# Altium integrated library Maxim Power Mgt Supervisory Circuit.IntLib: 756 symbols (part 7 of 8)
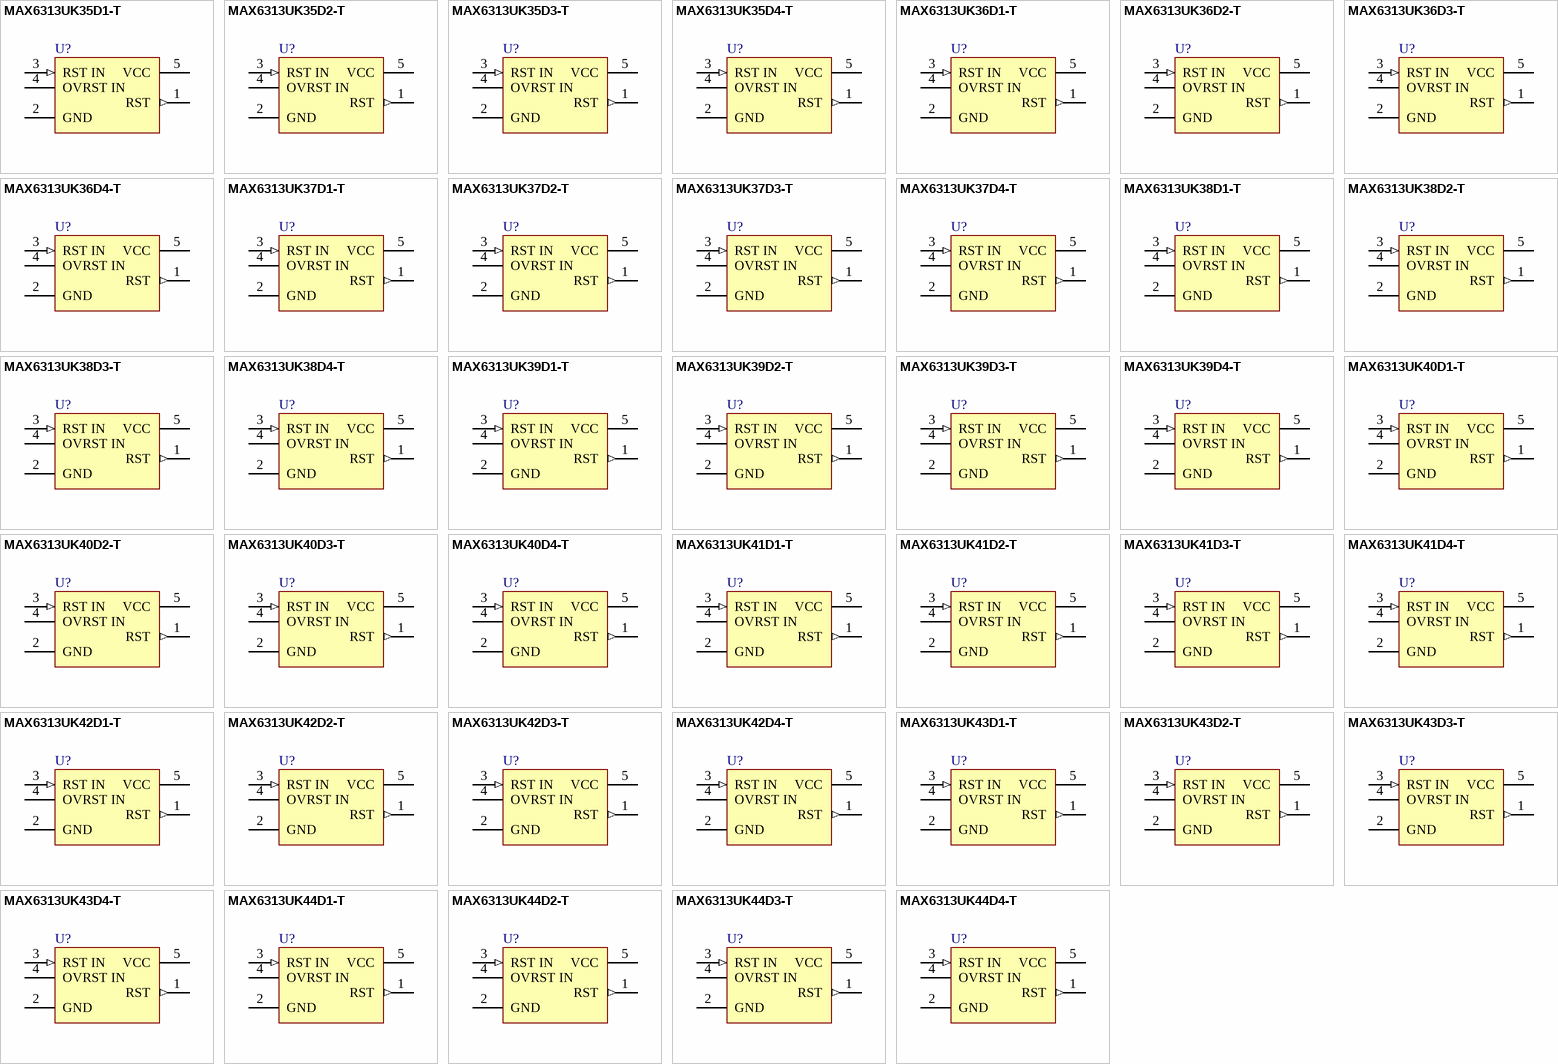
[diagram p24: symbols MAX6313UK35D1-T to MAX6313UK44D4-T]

## MAX6313UK36D3-T
designator U?
5-Pin, Multiple-Input, Programmable Reset IC
footprint SOT23-5_N (SOT23, 5-Leads, Body 2.9x1.6mm, Pitch 0.95mm, Lead Span 2.8mm, IPC Medium Density)
footprint SOT23-5_L (SOT23, 5-Leads, Body 2.9x1.6mm, Pitch 0.95mm, Lead Span 2.8mm, IPC High Density)
footprint SOT23-5_M (SOT23, 5-Leads, Body 2.9x1.6mm, Pitch 0.95mm, Lead Span 2.8mm, IPC Low Density)
pins: 1 RST (out), 2 GND (power), 3 RST IN (in), 4 OVRST IN, 5 VCC (power)

## MAX6313UK36D4-T
designator U?
5-Pin, Multiple-Input, Programmable Reset IC
footprint SOT23-5_N (SOT23, 5-Leads, Body 2.9x1.6mm, Pitch 0.95mm, Lead Span 2.8mm, IPC Medium Density)
footprint SOT23-5_L (SOT23, 5-Leads, Body 2.9x1.6mm, Pitch 0.95mm, Lead Span 2.8mm, IPC High Density)
footprint SOT23-5_M (SOT23, 5-Leads, Body 2.9x1.6mm, Pitch 0.95mm, Lead Span 2.8mm, IPC Low Density)
pins: 1 RST (out), 2 GND (power), 3 RST IN (in), 4 OVRST IN, 5 VCC (power)

## MAX6313UK37D1-T
designator U?
5-Pin, Multiple-Input, Programmable Reset IC
footprint SOT23-5_N (SOT23, 5-Leads, Body 2.9x1.6mm, Pitch 0.95mm, Lead Span 2.8mm, IPC Medium Density)
footprint SOT23-5_L (SOT23, 5-Leads, Body 2.9x1.6mm, Pitch 0.95mm, Lead Span 2.8mm, IPC High Density)
footprint SOT23-5_M (SOT23, 5-Leads, Body 2.9x1.6mm, Pitch 0.95mm, Lead Span 2.8mm, IPC Low Density)
pins: 1 RST (out), 2 GND (power), 3 RST IN (in), 4 OVRST IN, 5 VCC (power)

## MAX6313UK37D2-T
designator U?
5-Pin, Multiple-Input, Programmable Reset IC
footprint SOT23-5_N (SOT23, 5-Leads, Body 2.9x1.6mm, Pitch 0.95mm, Lead Span 2.8mm, IPC Medium Density)
footprint SOT23-5_L (SOT23, 5-Leads, Body 2.9x1.6mm, Pitch 0.95mm, Lead Span 2.8mm, IPC High Density)
footprint SOT23-5_M (SOT23, 5-Leads, Body 2.9x1.6mm, Pitch 0.95mm, Lead Span 2.8mm, IPC Low Density)
pins: 1 RST (out), 2 GND (power), 3 RST IN (in), 4 OVRST IN, 5 VCC (power)

## MAX6313UK37D3-T
designator U?
5-Pin, Multiple-Input, Programmable Reset IC
footprint SOT23-5_N (SOT23, 5-Leads, Body 2.9x1.6mm, Pitch 0.95mm, Lead Span 2.8mm, IPC Medium Density)
footprint SOT23-5_L (SOT23, 5-Leads, Body 2.9x1.6mm, Pitch 0.95mm, Lead Span 2.8mm, IPC High Density)
footprint SOT23-5_M (SOT23, 5-Leads, Body 2.9x1.6mm, Pitch 0.95mm, Lead Span 2.8mm, IPC Low Density)
pins: 1 RST (out), 2 GND (power), 3 RST IN (in), 4 OVRST IN, 5 VCC (power)

## MAX6313UK37D4-T
designator U?
5-Pin, Multiple-Input, Programmable Reset IC
footprint SOT23-5_N (SOT23, 5-Leads, Body 2.9x1.6mm, Pitch 0.95mm, Lead Span 2.8mm, IPC Medium Density)
footprint SOT23-5_L (SOT23, 5-Leads, Body 2.9x1.6mm, Pitch 0.95mm, Lead Span 2.8mm, IPC High Density)
footprint SOT23-5_M (SOT23, 5-Leads, Body 2.9x1.6mm, Pitch 0.95mm, Lead Span 2.8mm, IPC Low Density)
pins: 1 RST (out), 2 GND (power), 3 RST IN (in), 4 OVRST IN, 5 VCC (power)

## MAX6313UK38D1-T
designator U?
5-Pin, Multiple-Input, Programmable Reset IC
footprint SOT23-5_N (SOT23, 5-Leads, Body 2.9x1.6mm, Pitch 0.95mm, Lead Span 2.8mm, IPC Medium Density)
footprint SOT23-5_L (SOT23, 5-Leads, Body 2.9x1.6mm, Pitch 0.95mm, Lead Span 2.8mm, IPC High Density)
footprint SOT23-5_M (SOT23, 5-Leads, Body 2.9x1.6mm, Pitch 0.95mm, Lead Span 2.8mm, IPC Low Density)
pins: 1 RST (out), 2 GND (power), 3 RST IN (in), 4 OVRST IN, 5 VCC (power)

## MAX6313UK38D2-T
designator U?
5-Pin, Multiple-Input, Programmable Reset IC
footprint SOT23-5_N (SOT23, 5-Leads, Body 2.9x1.6mm, Pitch 0.95mm, Lead Span 2.8mm, IPC Medium Density)
footprint SOT23-5_L (SOT23, 5-Leads, Body 2.9x1.6mm, Pitch 0.95mm, Lead Span 2.8mm, IPC High Density)
footprint SOT23-5_M (SOT23, 5-Leads, Body 2.9x1.6mm, Pitch 0.95mm, Lead Span 2.8mm, IPC Low Density)
pins: 1 RST (out), 2 GND (power), 3 RST IN (in), 4 OVRST IN, 5 VCC (power)

## MAX6313UK38D3-T
designator U?
5-Pin, Multiple-Input, Programmable Reset IC
footprint SOT23-5_N (SOT23, 5-Leads, Body 2.9x1.6mm, Pitch 0.95mm, Lead Span 2.8mm, IPC Medium Density)
footprint SOT23-5_L (SOT23, 5-Leads, Body 2.9x1.6mm, Pitch 0.95mm, Lead Span 2.8mm, IPC High Density)
footprint SOT23-5_M (SOT23, 5-Leads, Body 2.9x1.6mm, Pitch 0.95mm, Lead Span 2.8mm, IPC Low Density)
pins: 1 RST (out), 2 GND (power), 3 RST IN (in), 4 OVRST IN, 5 VCC (power)

## MAX6313UK38D4-T
designator U?
5-Pin, Multiple-Input, Programmable Reset IC
footprint SOT23-5_N (SOT23, 5-Leads, Body 2.9x1.6mm, Pitch 0.95mm, Lead Span 2.8mm, IPC Medium Density)
footprint SOT23-5_L (SOT23, 5-Leads, Body 2.9x1.6mm, Pitch 0.95mm, Lead Span 2.8mm, IPC High Density)
footprint SOT23-5_M (SOT23, 5-Leads, Body 2.9x1.6mm, Pitch 0.95mm, Lead Span 2.8mm, IPC Low Density)
pins: 1 RST (out), 2 GND (power), 3 RST IN (in), 4 OVRST IN, 5 VCC (power)

## MAX6313UK39D1-T
designator U?
5-Pin, Multiple-Input, Programmable Reset IC
footprint SOT23-5_N (SOT23, 5-Leads, Body 2.9x1.6mm, Pitch 0.95mm, Lead Span 2.8mm, IPC Medium Density)
footprint SOT23-5_L (SOT23, 5-Leads, Body 2.9x1.6mm, Pitch 0.95mm, Lead Span 2.8mm, IPC High Density)
footprint SOT23-5_M (SOT23, 5-Leads, Body 2.9x1.6mm, Pitch 0.95mm, Lead Span 2.8mm, IPC Low Density)
pins: 1 RST (out), 2 GND (power), 3 RST IN (in), 4 OVRST IN, 5 VCC (power)

## MAX6313UK39D2-T
designator U?
5-Pin, Multiple-Input, Programmable Reset IC
footprint SOT23-5_N (SOT23, 5-Leads, Body 2.9x1.6mm, Pitch 0.95mm, Lead Span 2.8mm, IPC Medium Density)
footprint SOT23-5_L (SOT23, 5-Leads, Body 2.9x1.6mm, Pitch 0.95mm, Lead Span 2.8mm, IPC High Density)
footprint SOT23-5_M (SOT23, 5-Leads, Body 2.9x1.6mm, Pitch 0.95mm, Lead Span 2.8mm, IPC Low Density)
pins: 1 RST (out), 2 GND (power), 3 RST IN (in), 4 OVRST IN, 5 VCC (power)

## MAX6313UK39D3-T
designator U?
5-Pin, Multiple-Input, Programmable Reset IC
footprint SOT23-5_N (SOT23, 5-Leads, Body 2.9x1.6mm, Pitch 0.95mm, Lead Span 2.8mm, IPC Medium Density)
footprint SOT23-5_L (SOT23, 5-Leads, Body 2.9x1.6mm, Pitch 0.95mm, Lead Span 2.8mm, IPC High Density)
footprint SOT23-5_M (SOT23, 5-Leads, Body 2.9x1.6mm, Pitch 0.95mm, Lead Span 2.8mm, IPC Low Density)
pins: 1 RST (out), 2 GND (power), 3 RST IN (in), 4 OVRST IN, 5 VCC (power)

## MAX6313UK39D4-T
designator U?
5-Pin, Multiple-Input, Programmable Reset IC
footprint SOT23-5_N (SOT23, 5-Leads, Body 2.9x1.6mm, Pitch 0.95mm, Lead Span 2.8mm, IPC Medium Density)
footprint SOT23-5_L (SOT23, 5-Leads, Body 2.9x1.6mm, Pitch 0.95mm, Lead Span 2.8mm, IPC High Density)
footprint SOT23-5_M (SOT23, 5-Leads, Body 2.9x1.6mm, Pitch 0.95mm, Lead Span 2.8mm, IPC Low Density)
pins: 1 RST (out), 2 GND (power), 3 RST IN (in), 4 OVRST IN, 5 VCC (power)

## MAX6313UK40D1-T
designator U?
5-Pin, Multiple-Input, Programmable Reset IC
footprint SOT23-5_N (SOT23, 5-Leads, Body 2.9x1.6mm, Pitch 0.95mm, Lead Span 2.8mm, IPC Medium Density)
footprint SOT23-5_L (SOT23, 5-Leads, Body 2.9x1.6mm, Pitch 0.95mm, Lead Span 2.8mm, IPC High Density)
footprint SOT23-5_M (SOT23, 5-Leads, Body 2.9x1.6mm, Pitch 0.95mm, Lead Span 2.8mm, IPC Low Density)
pins: 1 RST (out), 2 GND (power), 3 RST IN (in), 4 OVRST IN, 5 VCC (power)

## MAX6313UK40D2-T
designator U?
5-Pin, Multiple-Input, Programmable Reset IC
footprint SOT23-5_N (SOT23, 5-Leads, Body 2.9x1.6mm, Pitch 0.95mm, Lead Span 2.8mm, IPC Medium Density)
footprint SOT23-5_L (SOT23, 5-Leads, Body 2.9x1.6mm, Pitch 0.95mm, Lead Span 2.8mm, IPC High Density)
footprint SOT23-5_M (SOT23, 5-Leads, Body 2.9x1.6mm, Pitch 0.95mm, Lead Span 2.8mm, IPC Low Density)
pins: 1 RST (out), 2 GND (power), 3 RST IN (in), 4 OVRST IN, 5 VCC (power)

## MAX6313UK40D3-T
designator U?
5-Pin, Multiple-Input, Programmable Reset IC
footprint SOT23-5_N (SOT23, 5-Leads, Body 2.9x1.6mm, Pitch 0.95mm, Lead Span 2.8mm, IPC Medium Density)
footprint SOT23-5_L (SOT23, 5-Leads, Body 2.9x1.6mm, Pitch 0.95mm, Lead Span 2.8mm, IPC High Density)
footprint SOT23-5_M (SOT23, 5-Leads, Body 2.9x1.6mm, Pitch 0.95mm, Lead Span 2.8mm, IPC Low Density)
pins: 1 RST (out), 2 GND (power), 3 RST IN (in), 4 OVRST IN, 5 VCC (power)

## MAX6313UK40D4-T
designator U?
5-Pin, Multiple-Input, Programmable Reset IC
footprint SOT23-5_N (SOT23, 5-Leads, Body 2.9x1.6mm, Pitch 0.95mm, Lead Span 2.8mm, IPC Medium Density)
footprint SOT23-5_L (SOT23, 5-Leads, Body 2.9x1.6mm, Pitch 0.95mm, Lead Span 2.8mm, IPC High Density)
footprint SOT23-5_M (SOT23, 5-Leads, Body 2.9x1.6mm, Pitch 0.95mm, Lead Span 2.8mm, IPC Low Density)
pins: 1 RST (out), 2 GND (power), 3 RST IN (in), 4 OVRST IN, 5 VCC (power)

## MAX6313UK41D1-T
designator U?
5-Pin, Multiple-Input, Programmable Reset IC
footprint SOT23-5_N (SOT23, 5-Leads, Body 2.9x1.6mm, Pitch 0.95mm, Lead Span 2.8mm, IPC Medium Density)
footprint SOT23-5_L (SOT23, 5-Leads, Body 2.9x1.6mm, Pitch 0.95mm, Lead Span 2.8mm, IPC High Density)
footprint SOT23-5_M (SOT23, 5-Leads, Body 2.9x1.6mm, Pitch 0.95mm, Lead Span 2.8mm, IPC Low Density)
pins: 1 RST (out), 2 GND (power), 3 RST IN (in), 4 OVRST IN, 5 VCC (power)

## MAX6313UK41D2-T
designator U?
5-Pin, Multiple-Input, Programmable Reset IC
footprint SOT23-5_N (SOT23, 5-Leads, Body 2.9x1.6mm, Pitch 0.95mm, Lead Span 2.8mm, IPC Medium Density)
footprint SOT23-5_L (SOT23, 5-Leads, Body 2.9x1.6mm, Pitch 0.95mm, Lead Span 2.8mm, IPC High Density)
footprint SOT23-5_M (SOT23, 5-Leads, Body 2.9x1.6mm, Pitch 0.95mm, Lead Span 2.8mm, IPC Low Density)
pins: 1 RST (out), 2 GND (power), 3 RST IN (in), 4 OVRST IN, 5 VCC (power)

## MAX6313UK41D3-T
designator U?
5-Pin, Multiple-Input, Programmable Reset IC
footprint SOT23-5_N (SOT23, 5-Leads, Body 2.9x1.6mm, Pitch 0.95mm, Lead Span 2.8mm, IPC Medium Density)
footprint SOT23-5_L (SOT23, 5-Leads, Body 2.9x1.6mm, Pitch 0.95mm, Lead Span 2.8mm, IPC High Density)
footprint SOT23-5_M (SOT23, 5-Leads, Body 2.9x1.6mm, Pitch 0.95mm, Lead Span 2.8mm, IPC Low Density)
pins: 1 RST (out), 2 GND (power), 3 RST IN (in), 4 OVRST IN, 5 VCC (power)

## MAX6313UK41D4-T
designator U?
5-Pin, Multiple-Input, Programmable Reset IC
footprint SOT23-5_N (SOT23, 5-Leads, Body 2.9x1.6mm, Pitch 0.95mm, Lead Span 2.8mm, IPC Medium Density)
footprint SOT23-5_L (SOT23, 5-Leads, Body 2.9x1.6mm, Pitch 0.95mm, Lead Span 2.8mm, IPC High Density)
footprint SOT23-5_M (SOT23, 5-Leads, Body 2.9x1.6mm, Pitch 0.95mm, Lead Span 2.8mm, IPC Low Density)
pins: 1 RST (out), 2 GND (power), 3 RST IN (in), 4 OVRST IN, 5 VCC (power)

## MAX6313UK42D1-T
designator U?
5-Pin, Multiple-Input, Programmable Reset IC
footprint SOT23-5_N (SOT23, 5-Leads, Body 2.9x1.6mm, Pitch 0.95mm, Lead Span 2.8mm, IPC Medium Density)
footprint SOT23-5_L (SOT23, 5-Leads, Body 2.9x1.6mm, Pitch 0.95mm, Lead Span 2.8mm, IPC High Density)
footprint SOT23-5_M (SOT23, 5-Leads, Body 2.9x1.6mm, Pitch 0.95mm, Lead Span 2.8mm, IPC Low Density)
pins: 1 RST (out), 2 GND (power), 3 RST IN (in), 4 OVRST IN, 5 VCC (power)

## MAX6313UK42D2-T
designator U?
5-Pin, Multiple-Input, Programmable Reset IC
footprint SOT23-5_N (SOT23, 5-Leads, Body 2.9x1.6mm, Pitch 0.95mm, Lead Span 2.8mm, IPC Medium Density)
footprint SOT23-5_L (SOT23, 5-Leads, Body 2.9x1.6mm, Pitch 0.95mm, Lead Span 2.8mm, IPC High Density)
footprint SOT23-5_M (SOT23, 5-Leads, Body 2.9x1.6mm, Pitch 0.95mm, Lead Span 2.8mm, IPC Low Density)
pins: 1 RST (out), 2 GND (power), 3 RST IN (in), 4 OVRST IN, 5 VCC (power)

## MAX6313UK42D3-T
designator U?
5-Pin, Multiple-Input, Programmable Reset IC
footprint SOT23-5_N (SOT23, 5-Leads, Body 2.9x1.6mm, Pitch 0.95mm, Lead Span 2.8mm, IPC Medium Density)
footprint SOT23-5_L (SOT23, 5-Leads, Body 2.9x1.6mm, Pitch 0.95mm, Lead Span 2.8mm, IPC High Density)
footprint SOT23-5_M (SOT23, 5-Leads, Body 2.9x1.6mm, Pitch 0.95mm, Lead Span 2.8mm, IPC Low Density)
pins: 1 RST (out), 2 GND (power), 3 RST IN (in), 4 OVRST IN, 5 VCC (power)

## MAX6313UK42D4-T
designator U?
5-Pin, Multiple-Input, Programmable Reset IC
footprint SOT23-5_N (SOT23, 5-Leads, Body 2.9x1.6mm, Pitch 0.95mm, Lead Span 2.8mm, IPC Medium Density)
footprint SOT23-5_L (SOT23, 5-Leads, Body 2.9x1.6mm, Pitch 0.95mm, Lead Span 2.8mm, IPC High Density)
footprint SOT23-5_M (SOT23, 5-Leads, Body 2.9x1.6mm, Pitch 0.95mm, Lead Span 2.8mm, IPC Low Density)
pins: 1 RST (out), 2 GND (power), 3 RST IN (in), 4 OVRST IN, 5 VCC (power)

## MAX6313UK43D1-T
designator U?
5-Pin, Multiple-Input, Programmable Reset IC
footprint SOT23-5_N (SOT23, 5-Leads, Body 2.9x1.6mm, Pitch 0.95mm, Lead Span 2.8mm, IPC Medium Density)
footprint SOT23-5_L (SOT23, 5-Leads, Body 2.9x1.6mm, Pitch 0.95mm, Lead Span 2.8mm, IPC High Density)
footprint SOT23-5_M (SOT23, 5-Leads, Body 2.9x1.6mm, Pitch 0.95mm, Lead Span 2.8mm, IPC Low Density)
pins: 1 RST (out), 2 GND (power), 3 RST IN (in), 4 OVRST IN, 5 VCC (power)

## MAX6313UK43D2-T
designator U?
5-Pin, Multiple-Input, Programmable Reset IC
footprint SOT23-5_N (SOT23, 5-Leads, Body 2.9x1.6mm, Pitch 0.95mm, Lead Span 2.8mm, IPC Medium Density)
footprint SOT23-5_L (SOT23, 5-Leads, Body 2.9x1.6mm, Pitch 0.95mm, Lead Span 2.8mm, IPC High Density)
footprint SOT23-5_M (SOT23, 5-Leads, Body 2.9x1.6mm, Pitch 0.95mm, Lead Span 2.8mm, IPC Low Density)
pins: 1 RST (out), 2 GND (power), 3 RST IN (in), 4 OVRST IN, 5 VCC (power)

## MAX6313UK43D3-T
designator U?
5-Pin, Multiple-Input, Programmable Reset IC
footprint SOT23-5_N (SOT23, 5-Leads, Body 2.9x1.6mm, Pitch 0.95mm, Lead Span 2.8mm, IPC Medium Density)
footprint SOT23-5_L (SOT23, 5-Leads, Body 2.9x1.6mm, Pitch 0.95mm, Lead Span 2.8mm, IPC High Density)
footprint SOT23-5_M (SOT23, 5-Leads, Body 2.9x1.6mm, Pitch 0.95mm, Lead Span 2.8mm, IPC Low Density)
pins: 1 RST (out), 2 GND (power), 3 RST IN (in), 4 OVRST IN, 5 VCC (power)

## MAX6313UK43D4-T
designator U?
5-Pin, Multiple-Input, Programmable Reset IC
footprint SOT23-5_N (SOT23, 5-Leads, Body 2.9x1.6mm, Pitch 0.95mm, Lead Span 2.8mm, IPC Medium Density)
footprint SOT23-5_L (SOT23, 5-Leads, Body 2.9x1.6mm, Pitch 0.95mm, Lead Span 2.8mm, IPC High Density)
footprint SOT23-5_M (SOT23, 5-Leads, Body 2.9x1.6mm, Pitch 0.95mm, Lead Span 2.8mm, IPC Low Density)
pins: 1 RST (out), 2 GND (power), 3 RST IN (in), 4 OVRST IN, 5 VCC (power)

## MAX6313UK44D1-T
designator U?
5-Pin, Multiple-Input, Programmable Reset IC
footprint SOT23-5_N (SOT23, 5-Leads, Body 2.9x1.6mm, Pitch 0.95mm, Lead Span 2.8mm, IPC Medium Density)
footprint SOT23-5_L (SOT23, 5-Leads, Body 2.9x1.6mm, Pitch 0.95mm, Lead Span 2.8mm, IPC High Density)
footprint SOT23-5_M (SOT23, 5-Leads, Body 2.9x1.6mm, Pitch 0.95mm, Lead Span 2.8mm, IPC Low Density)
pins: 1 RST (out), 2 GND (power), 3 RST IN (in), 4 OVRST IN, 5 VCC (power)

## MAX6313UK44D2-T
designator U?
5-Pin, Multiple-Input, Programmable Reset IC
footprint SOT23-5_N (SOT23, 5-Leads, Body 2.9x1.6mm, Pitch 0.95mm, Lead Span 2.8mm, IPC Medium Density)
footprint SOT23-5_L (SOT23, 5-Leads, Body 2.9x1.6mm, Pitch 0.95mm, Lead Span 2.8mm, IPC High Density)
footprint SOT23-5_M (SOT23, 5-Leads, Body 2.9x1.6mm, Pitch 0.95mm, Lead Span 2.8mm, IPC Low Density)
pins: 1 RST (out), 2 GND (power), 3 RST IN (in), 4 OVRST IN, 5 VCC (power)

## MAX6313UK44D3-T
designator U?
5-Pin, Multiple-Input, Programmable Reset IC
footprint SOT23-5_N (SOT23, 5-Leads, Body 2.9x1.6mm, Pitch 0.95mm, Lead Span 2.8mm, IPC Medium Density)
footprint SOT23-5_L (SOT23, 5-Leads, Body 2.9x1.6mm, Pitch 0.95mm, Lead Span 2.8mm, IPC High Density)
footprint SOT23-5_M (SOT23, 5-Leads, Body 2.9x1.6mm, Pitch 0.95mm, Lead Span 2.8mm, IPC Low Density)
pins: 1 RST (out), 2 GND (power), 3 RST IN (in), 4 OVRST IN, 5 VCC (power)

## MAX6313UK44D4-T
designator U?
5-Pin, Multiple-Input, Programmable Reset IC
footprint SOT23-5_N (SOT23, 5-Leads, Body 2.9x1.6mm, Pitch 0.95mm, Lead Span 2.8mm, IPC Medium Density)
footprint SOT23-5_L (SOT23, 5-Leads, Body 2.9x1.6mm, Pitch 0.95mm, Lead Span 2.8mm, IPC High Density)
footprint SOT23-5_M (SOT23, 5-Leads, Body 2.9x1.6mm, Pitch 0.95mm, Lead Span 2.8mm, IPC Low Density)
pins: 1 RST (out), 2 GND (power), 3 RST IN (in), 4 OVRST IN, 5 VCC (power)

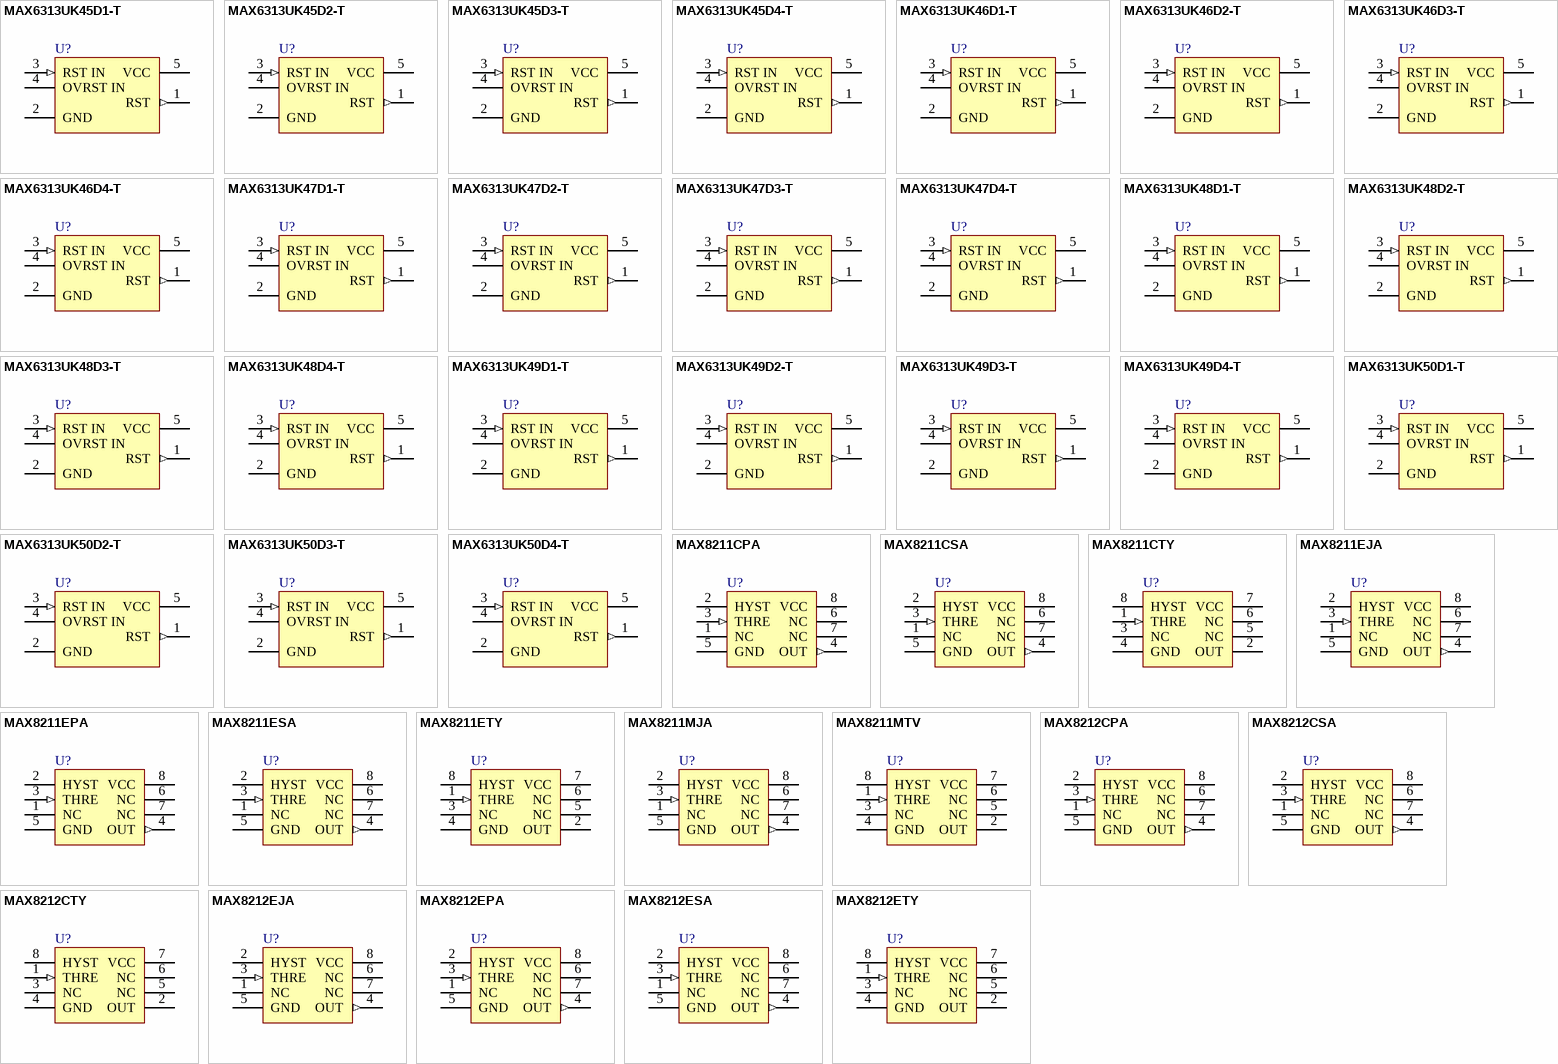
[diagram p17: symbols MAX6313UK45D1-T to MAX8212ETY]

## MAX6313UK45D1-T
designator U?
5-Pin, Multiple-Input, Programmable Reset IC
footprint SOT23-5_N (SOT23, 5-Leads, Body 2.9x1.6mm, Pitch 0.95mm, Lead Span 2.8mm, IPC Medium Density)
footprint SOT23-5_L (SOT23, 5-Leads, Body 2.9x1.6mm, Pitch 0.95mm, Lead Span 2.8mm, IPC High Density)
footprint SOT23-5_M (SOT23, 5-Leads, Body 2.9x1.6mm, Pitch 0.95mm, Lead Span 2.8mm, IPC Low Density)
pins: 1 RST (out), 2 GND (power), 3 RST IN (in), 4 OVRST IN, 5 VCC (power)

## MAX6313UK45D2-T
designator U?
5-Pin, Multiple-Input, Programmable Reset IC
footprint SOT23-5_N (SOT23, 5-Leads, Body 2.9x1.6mm, Pitch 0.95mm, Lead Span 2.8mm, IPC Medium Density)
footprint SOT23-5_L (SOT23, 5-Leads, Body 2.9x1.6mm, Pitch 0.95mm, Lead Span 2.8mm, IPC High Density)
footprint SOT23-5_M (SOT23, 5-Leads, Body 2.9x1.6mm, Pitch 0.95mm, Lead Span 2.8mm, IPC Low Density)
pins: 1 RST (out), 2 GND (power), 3 RST IN (in), 4 OVRST IN, 5 VCC (power)

## MAX6313UK45D3-T
designator U?
5-Pin, Multiple-Input, Programmable Reset IC
footprint SOT23-5_N (SOT23, 5-Leads, Body 2.9x1.6mm, Pitch 0.95mm, Lead Span 2.8mm, IPC Medium Density)
footprint SOT23-5_L (SOT23, 5-Leads, Body 2.9x1.6mm, Pitch 0.95mm, Lead Span 2.8mm, IPC High Density)
footprint SOT23-5_M (SOT23, 5-Leads, Body 2.9x1.6mm, Pitch 0.95mm, Lead Span 2.8mm, IPC Low Density)
pins: 1 RST (out), 2 GND (power), 3 RST IN (in), 4 OVRST IN, 5 VCC (power)

## MAX6313UK45D4-T
designator U?
5-Pin, Multiple-Input, Programmable Reset IC
footprint SOT23-5_N (SOT23, 5-Leads, Body 2.9x1.6mm, Pitch 0.95mm, Lead Span 2.8mm, IPC Medium Density)
footprint SOT23-5_L (SOT23, 5-Leads, Body 2.9x1.6mm, Pitch 0.95mm, Lead Span 2.8mm, IPC High Density)
footprint SOT23-5_M (SOT23, 5-Leads, Body 2.9x1.6mm, Pitch 0.95mm, Lead Span 2.8mm, IPC Low Density)
pins: 1 RST (out), 2 GND (power), 3 RST IN (in), 4 OVRST IN, 5 VCC (power)

## MAX6313UK46D1-T
designator U?
5-Pin, Multiple-Input, Programmable Reset IC
footprint SOT23-5_N (SOT23, 5-Leads, Body 2.9x1.6mm, Pitch 0.95mm, Lead Span 2.8mm, IPC Medium Density)
footprint SOT23-5_L (SOT23, 5-Leads, Body 2.9x1.6mm, Pitch 0.95mm, Lead Span 2.8mm, IPC High Density)
footprint SOT23-5_M (SOT23, 5-Leads, Body 2.9x1.6mm, Pitch 0.95mm, Lead Span 2.8mm, IPC Low Density)
pins: 1 RST (out), 2 GND (power), 3 RST IN (in), 4 OVRST IN, 5 VCC (power)

## MAX6313UK46D2-T
designator U?
5-Pin, Multiple-Input, Programmable Reset IC
footprint SOT23-5_N (SOT23, 5-Leads, Body 2.9x1.6mm, Pitch 0.95mm, Lead Span 2.8mm, IPC Medium Density)
footprint SOT23-5_L (SOT23, 5-Leads, Body 2.9x1.6mm, Pitch 0.95mm, Lead Span 2.8mm, IPC High Density)
footprint SOT23-5_M (SOT23, 5-Leads, Body 2.9x1.6mm, Pitch 0.95mm, Lead Span 2.8mm, IPC Low Density)
pins: 1 RST (out), 2 GND (power), 3 RST IN (in), 4 OVRST IN, 5 VCC (power)

## MAX6313UK46D3-T
designator U?
5-Pin, Multiple-Input, Programmable Reset IC
footprint SOT23-5_N (SOT23, 5-Leads, Body 2.9x1.6mm, Pitch 0.95mm, Lead Span 2.8mm, IPC Medium Density)
footprint SOT23-5_L (SOT23, 5-Leads, Body 2.9x1.6mm, Pitch 0.95mm, Lead Span 2.8mm, IPC High Density)
footprint SOT23-5_M (SOT23, 5-Leads, Body 2.9x1.6mm, Pitch 0.95mm, Lead Span 2.8mm, IPC Low Density)
pins: 1 RST (out), 2 GND (power), 3 RST IN (in), 4 OVRST IN, 5 VCC (power)

## MAX6313UK46D4-T
designator U?
5-Pin, Multiple-Input, Programmable Reset IC
footprint SOT23-5_N (SOT23, 5-Leads, Body 2.9x1.6mm, Pitch 0.95mm, Lead Span 2.8mm, IPC Medium Density)
footprint SOT23-5_L (SOT23, 5-Leads, Body 2.9x1.6mm, Pitch 0.95mm, Lead Span 2.8mm, IPC High Density)
footprint SOT23-5_M (SOT23, 5-Leads, Body 2.9x1.6mm, Pitch 0.95mm, Lead Span 2.8mm, IPC Low Density)
pins: 1 RST (out), 2 GND (power), 3 RST IN (in), 4 OVRST IN, 5 VCC (power)

## MAX6313UK47D1-T
designator U?
5-Pin, Multiple-Input, Programmable Reset IC
footprint SOT23-5_N (SOT23, 5-Leads, Body 2.9x1.6mm, Pitch 0.95mm, Lead Span 2.8mm, IPC Medium Density)
footprint SOT23-5_L (SOT23, 5-Leads, Body 2.9x1.6mm, Pitch 0.95mm, Lead Span 2.8mm, IPC High Density)
footprint SOT23-5_M (SOT23, 5-Leads, Body 2.9x1.6mm, Pitch 0.95mm, Lead Span 2.8mm, IPC Low Density)
pins: 1 RST (out), 2 GND (power), 3 RST IN (in), 4 OVRST IN, 5 VCC (power)

## MAX6313UK47D2-T
designator U?
5-Pin, Multiple-Input, Programmable Reset IC
footprint SOT23-5_N (SOT23, 5-Leads, Body 2.9x1.6mm, Pitch 0.95mm, Lead Span 2.8mm, IPC Medium Density)
footprint SOT23-5_L (SOT23, 5-Leads, Body 2.9x1.6mm, Pitch 0.95mm, Lead Span 2.8mm, IPC High Density)
footprint SOT23-5_M (SOT23, 5-Leads, Body 2.9x1.6mm, Pitch 0.95mm, Lead Span 2.8mm, IPC Low Density)
pins: 1 RST (out), 2 GND (power), 3 RST IN (in), 4 OVRST IN, 5 VCC (power)

## MAX6313UK47D3-T
designator U?
5-Pin, Multiple-Input, Programmable Reset IC
footprint SOT23-5_N (SOT23, 5-Leads, Body 2.9x1.6mm, Pitch 0.95mm, Lead Span 2.8mm, IPC Medium Density)
footprint SOT23-5_L (SOT23, 5-Leads, Body 2.9x1.6mm, Pitch 0.95mm, Lead Span 2.8mm, IPC High Density)
footprint SOT23-5_M (SOT23, 5-Leads, Body 2.9x1.6mm, Pitch 0.95mm, Lead Span 2.8mm, IPC Low Density)
pins: 1 RST (out), 2 GND (power), 3 RST IN (in), 4 OVRST IN, 5 VCC (power)

## MAX6313UK47D4-T
designator U?
5-Pin, Multiple-Input, Programmable Reset IC
footprint SOT23-5_N (SOT23, 5-Leads, Body 2.9x1.6mm, Pitch 0.95mm, Lead Span 2.8mm, IPC Medium Density)
footprint SOT23-5_L (SOT23, 5-Leads, Body 2.9x1.6mm, Pitch 0.95mm, Lead Span 2.8mm, IPC High Density)
footprint SOT23-5_M (SOT23, 5-Leads, Body 2.9x1.6mm, Pitch 0.95mm, Lead Span 2.8mm, IPC Low Density)
pins: 1 RST (out), 2 GND (power), 3 RST IN (in), 4 OVRST IN, 5 VCC (power)

## MAX6313UK48D1-T
designator U?
5-Pin, Multiple-Input, Programmable Reset IC
footprint SOT23-5_N (SOT23, 5-Leads, Body 2.9x1.6mm, Pitch 0.95mm, Lead Span 2.8mm, IPC Medium Density)
footprint SOT23-5_L (SOT23, 5-Leads, Body 2.9x1.6mm, Pitch 0.95mm, Lead Span 2.8mm, IPC High Density)
footprint SOT23-5_M (SOT23, 5-Leads, Body 2.9x1.6mm, Pitch 0.95mm, Lead Span 2.8mm, IPC Low Density)
pins: 1 RST (out), 2 GND (power), 3 RST IN (in), 4 OVRST IN, 5 VCC (power)

## MAX6313UK48D2-T
designator U?
5-Pin, Multiple-Input, Programmable Reset IC
footprint SOT23-5_N (SOT23, 5-Leads, Body 2.9x1.6mm, Pitch 0.95mm, Lead Span 2.8mm, IPC Medium Density)
footprint SOT23-5_L (SOT23, 5-Leads, Body 2.9x1.6mm, Pitch 0.95mm, Lead Span 2.8mm, IPC High Density)
footprint SOT23-5_M (SOT23, 5-Leads, Body 2.9x1.6mm, Pitch 0.95mm, Lead Span 2.8mm, IPC Low Density)
pins: 1 RST (out), 2 GND (power), 3 RST IN (in), 4 OVRST IN, 5 VCC (power)

## MAX6313UK48D3-T
designator U?
5-Pin, Multiple-Input, Programmable Reset IC
footprint SOT23-5_N (SOT23, 5-Leads, Body 2.9x1.6mm, Pitch 0.95mm, Lead Span 2.8mm, IPC Medium Density)
footprint SOT23-5_L (SOT23, 5-Leads, Body 2.9x1.6mm, Pitch 0.95mm, Lead Span 2.8mm, IPC High Density)
footprint SOT23-5_M (SOT23, 5-Leads, Body 2.9x1.6mm, Pitch 0.95mm, Lead Span 2.8mm, IPC Low Density)
pins: 1 RST (out), 2 GND (power), 3 RST IN (in), 4 OVRST IN, 5 VCC (power)

## MAX6313UK48D4-T
designator U?
5-Pin, Multiple-Input, Programmable Reset IC
footprint SOT23-5_N (SOT23, 5-Leads, Body 2.9x1.6mm, Pitch 0.95mm, Lead Span 2.8mm, IPC Medium Density)
footprint SOT23-5_L (SOT23, 5-Leads, Body 2.9x1.6mm, Pitch 0.95mm, Lead Span 2.8mm, IPC High Density)
footprint SOT23-5_M (SOT23, 5-Leads, Body 2.9x1.6mm, Pitch 0.95mm, Lead Span 2.8mm, IPC Low Density)
pins: 1 RST (out), 2 GND (power), 3 RST IN (in), 4 OVRST IN, 5 VCC (power)

## MAX6313UK49D1-T
designator U?
5-Pin, Multiple-Input, Programmable Reset IC
footprint SOT23-5_N (SOT23, 5-Leads, Body 2.9x1.6mm, Pitch 0.95mm, Lead Span 2.8mm, IPC Medium Density)
footprint SOT23-5_L (SOT23, 5-Leads, Body 2.9x1.6mm, Pitch 0.95mm, Lead Span 2.8mm, IPC High Density)
footprint SOT23-5_M (SOT23, 5-Leads, Body 2.9x1.6mm, Pitch 0.95mm, Lead Span 2.8mm, IPC Low Density)
pins: 1 RST (out), 2 GND (power), 3 RST IN (in), 4 OVRST IN, 5 VCC (power)

## MAX6313UK49D2-T
designator U?
5-Pin, Multiple-Input, Programmable Reset IC
footprint SOT23-5_N (SOT23, 5-Leads, Body 2.9x1.6mm, Pitch 0.95mm, Lead Span 2.8mm, IPC Medium Density)
footprint SOT23-5_L (SOT23, 5-Leads, Body 2.9x1.6mm, Pitch 0.95mm, Lead Span 2.8mm, IPC High Density)
footprint SOT23-5_M (SOT23, 5-Leads, Body 2.9x1.6mm, Pitch 0.95mm, Lead Span 2.8mm, IPC Low Density)
pins: 1 RST (out), 2 GND (power), 3 RST IN (in), 4 OVRST IN, 5 VCC (power)

## MAX6313UK49D3-T
designator U?
5-Pin, Multiple-Input, Programmable Reset IC
footprint SOT23-5_N (SOT23, 5-Leads, Body 2.9x1.6mm, Pitch 0.95mm, Lead Span 2.8mm, IPC Medium Density)
footprint SOT23-5_L (SOT23, 5-Leads, Body 2.9x1.6mm, Pitch 0.95mm, Lead Span 2.8mm, IPC High Density)
footprint SOT23-5_M (SOT23, 5-Leads, Body 2.9x1.6mm, Pitch 0.95mm, Lead Span 2.8mm, IPC Low Density)
pins: 1 RST (out), 2 GND (power), 3 RST IN (in), 4 OVRST IN, 5 VCC (power)

## MAX6313UK49D4-T
designator U?
5-Pin, Multiple-Input, Programmable Reset IC
footprint SOT23-5_N (SOT23, 5-Leads, Body 2.9x1.6mm, Pitch 0.95mm, Lead Span 2.8mm, IPC Medium Density)
footprint SOT23-5_L (SOT23, 5-Leads, Body 2.9x1.6mm, Pitch 0.95mm, Lead Span 2.8mm, IPC High Density)
footprint SOT23-5_M (SOT23, 5-Leads, Body 2.9x1.6mm, Pitch 0.95mm, Lead Span 2.8mm, IPC Low Density)
pins: 1 RST (out), 2 GND (power), 3 RST IN (in), 4 OVRST IN, 5 VCC (power)

## MAX6313UK50D1-T
designator U?
5-Pin, Multiple-Input, Programmable Reset IC
footprint SOT23-5_N (SOT23, 5-Leads, Body 2.9x1.6mm, Pitch 0.95mm, Lead Span 2.8mm, IPC Medium Density)
footprint SOT23-5_L (SOT23, 5-Leads, Body 2.9x1.6mm, Pitch 0.95mm, Lead Span 2.8mm, IPC High Density)
footprint SOT23-5_M (SOT23, 5-Leads, Body 2.9x1.6mm, Pitch 0.95mm, Lead Span 2.8mm, IPC Low Density)
pins: 1 RST (out), 2 GND (power), 3 RST IN (in), 4 OVRST IN, 5 VCC (power)

## MAX6313UK50D2-T
designator U?
5-Pin, Multiple-Input, Programmable Reset IC
footprint SOT23-5_N (SOT23, 5-Leads, Body 2.9x1.6mm, Pitch 0.95mm, Lead Span 2.8mm, IPC Medium Density)
footprint SOT23-5_L (SOT23, 5-Leads, Body 2.9x1.6mm, Pitch 0.95mm, Lead Span 2.8mm, IPC High Density)
footprint SOT23-5_M (SOT23, 5-Leads, Body 2.9x1.6mm, Pitch 0.95mm, Lead Span 2.8mm, IPC Low Density)
pins: 1 RST (out), 2 GND (power), 3 RST IN (in), 4 OVRST IN, 5 VCC (power)

## MAX6313UK50D3-T
designator U?
5-Pin, Multiple-Input, Programmable Reset IC
footprint SOT23-5_N (SOT23, 5-Leads, Body 2.9x1.6mm, Pitch 0.95mm, Lead Span 2.8mm, IPC Medium Density)
footprint SOT23-5_L (SOT23, 5-Leads, Body 2.9x1.6mm, Pitch 0.95mm, Lead Span 2.8mm, IPC High Density)
footprint SOT23-5_M (SOT23, 5-Leads, Body 2.9x1.6mm, Pitch 0.95mm, Lead Span 2.8mm, IPC Low Density)
pins: 1 RST (out), 2 GND (power), 3 RST IN (in), 4 OVRST IN, 5 VCC (power)

## MAX6313UK50D4-T
designator U?
5-Pin, Multiple-Input, Programmable Reset IC
footprint SOT23-5_N (SOT23, 5-Leads, Body 2.9x1.6mm, Pitch 0.95mm, Lead Span 2.8mm, IPC Medium Density)
footprint SOT23-5_L (SOT23, 5-Leads, Body 2.9x1.6mm, Pitch 0.95mm, Lead Span 2.8mm, IPC High Density)
footprint SOT23-5_M (SOT23, 5-Leads, Body 2.9x1.6mm, Pitch 0.95mm, Lead Span 2.8mm, IPC Low Density)
pins: 1 RST (out), 2 GND (power), 3 RST IN (in), 4 OVRST IN, 5 VCC (power)

## MAX8211CPA
designator U?
Microprocessor Voltage Monitor with Programmable Voltage Detection
footprint PA8 (DIP, 8-Leads, Row Spacing 7.62mm, Pitch 2.54mm, Body 9.38x7.24mm)
3D model PA8 (DIP, 8-Pin, Row Spacing 7.62 mm, Pitch 2.54 mm)
pins: 1 NC, 2 HYST (oe), 3 THRE (in), 4 OUT (out), 5 GND (power), 6 NC, 7 NC, 8 VCC (power)

## MAX8211CSA
designator U?
Microprocessor Voltage Monitor with Programmable Voltage Detection
footprint NSO8_N (SOIC, 8-Leads, Body 4.9x3.9mm, Pitch 1.27mm, IPC Medium Density)
footprint NSO8_L (SOIC, 8-Leads, Body 4.9x3.9mm, Pitch 1.27mm, IPC High Density)
footprint NSO8_M (SOIC, 8-Leads, Body 4.9x3.9mm, Pitch 1.27mm, IPC Low Density)
3D model NSO8 (8-Pin Small Outline Integrated Circuit 1.27 mm Pitch)
pins: 1 NC, 2 HYST (oe), 3 THRE (in), 4 OUT (out), 5 GND (power), 6 NC, 7 NC, 8 VCC (power)

## MAX8211CTY
designator U?
Microprocessor Voltage Monitor with Programmable Voltage Detection
footprint TO-99 (Can; 8 Leads; Pin Circle Dia. 5.08 mm; Lead Dia. 0.48 mm (max))
pins: 1 THRE (in), 2 OUT (oc), 3 NC, 4 GND (power), 5 NC, 6 NC, 7 VCC (power), 8 HYST (oe)

## MAX8211EJA
designator U?
Microprocessor Voltage Monitor with Programmable Voltage Detection
footprint JA8 (DIP, 8-Leads, Row Spacing 7.62mm, Pitch 2.54mm, Body 9.91x6.73mm)
3D model PA8 (DIP, 8-Pin, Row Spacing 7.62 mm, Pitch 2.54 mm)
pins: 1 NC, 2 HYST (oe), 3 THRE (in), 4 OUT (out), 5 GND (power), 6 NC, 7 NC, 8 VCC (power)

## MAX8211EPA
designator U?
Microprocessor Voltage Monitor with Programmable Voltage Detection
footprint PA8 (DIP, 8-Leads, Row Spacing 7.62mm, Pitch 2.54mm, Body 9.38x7.24mm)
3D model PA8 (DIP, 8-Pin, Row Spacing 7.62 mm, Pitch 2.54 mm)
pins: 1 NC, 2 HYST (oe), 3 THRE (in), 4 OUT (out), 5 GND (power), 6 NC, 7 NC, 8 VCC (power)

## MAX8211ESA
designator U?
Microprocessor Voltage Monitor with Programmable Voltage Detection
footprint NSO8_N (SOIC, 8-Leads, Body 4.9x3.9mm, Pitch 1.27mm, IPC Medium Density)
footprint NSO8_L (SOIC, 8-Leads, Body 4.9x3.9mm, Pitch 1.27mm, IPC High Density)
footprint NSO8_M (SOIC, 8-Leads, Body 4.9x3.9mm, Pitch 1.27mm, IPC Low Density)
3D model NSO8 (8-Pin Small Outline Integrated Circuit 1.27 mm Pitch)
pins: 1 NC, 2 HYST (oe), 3 THRE (in), 4 OUT (out), 5 GND (power), 6 NC, 7 NC, 8 VCC (power)

## MAX8211ETY
designator U?
Microprocessor Voltage Monitor with Programmable Voltage Detection
footprint TO-99 (Can; 8 Leads; Pin Circle Dia. 5.08 mm; Lead Dia. 0.48 mm (max))
pins: 1 THRE (in), 2 OUT (oc), 3 NC, 4 GND (power), 5 NC, 6 NC, 7 VCC (power), 8 HYST (oe)

## MAX8211MJA
designator U?
Microprocessor Voltage Monitor with Programmable Voltage Detection
footprint JA8 (DIP, 8-Leads, Row Spacing 7.62mm, Pitch 2.54mm, Body 9.91x6.73mm)
3D model PA8 (DIP, 8-Pin, Row Spacing 7.62 mm, Pitch 2.54 mm)
pins: 1 NC, 2 HYST (oe), 3 THRE (in), 4 OUT (out), 5 GND (power), 6 NC, 7 NC, 8 VCC (power)

## MAX8211MTV
designator U?
Microprocessor Voltage Monitor with Programmable Voltage Detection
footprint TO-99 (Can; 8 Leads; Pin Circle Dia. 5.08 mm; Lead Dia. 0.48 mm (max))
pins: 1 THRE (in), 2 OUT (oc), 3 NC, 4 GND (power), 5 NC, 6 NC, 7 VCC (power), 8 HYST (oe)

## MAX8212CPA
designator U?
Microprocessor Voltage Monitor with Programmable Voltage Detection
footprint PA8 (DIP, 8-Leads, Row Spacing 7.62mm, Pitch 2.54mm, Body 9.38x7.24mm)
3D model PA8 (DIP, 8-Pin, Row Spacing 7.62 mm, Pitch 2.54 mm)
pins: 1 NC, 2 HYST (oe), 3 THRE (in), 4 OUT (out), 5 GND (power), 6 NC, 7 NC, 8 VCC (power)

## MAX8212CSA
designator U?
Microprocessor Voltage Monitor with Programmable Voltage Detection
footprint NSO8_N (SOIC, 8-Leads, Body 4.9x3.9mm, Pitch 1.27mm, IPC Medium Density)
footprint NSO8_L (SOIC, 8-Leads, Body 4.9x3.9mm, Pitch 1.27mm, IPC High Density)
footprint NSO8_M (SOIC, 8-Leads, Body 4.9x3.9mm, Pitch 1.27mm, IPC Low Density)
3D model NSO8 (8-Pin Small Outline Integrated Circuit 1.27 mm Pitch)
pins: 1 NC, 2 HYST (oe), 3 THRE (in), 4 OUT (out), 5 GND (power), 6 NC, 7 NC, 8 VCC (power)

## MAX8212CTY
designator U?
Microprocessor Voltage Monitor with Programmable Voltage Detection
footprint TO-99 (Can; 8 Leads; Pin Circle Dia. 5.08 mm; Lead Dia. 0.48 mm (max))
pins: 1 THRE (in), 2 OUT (oc), 3 NC, 4 GND (power), 5 NC, 6 NC, 7 VCC (power), 8 HYST (oe)

## MAX8212EJA
designator U?
Microprocessor Voltage Monitor with Programmable Voltage Detection
footprint JA8 (DIP, 8-Leads, Row Spacing 7.62mm, Pitch 2.54mm, Body 9.91x6.73mm)
3D model PA8 (DIP, 8-Pin, Row Spacing 7.62 mm, Pitch 2.54 mm)
pins: 1 NC, 2 HYST (oe), 3 THRE (in), 4 OUT (out), 5 GND (power), 6 NC, 7 NC, 8 VCC (power)

## MAX8212EPA
designator U?
Microprocessor Voltage Monitor with Programmable Voltage Detection
footprint PA8 (DIP, 8-Leads, Row Spacing 7.62mm, Pitch 2.54mm, Body 9.38x7.24mm)
3D model PA8 (DIP, 8-Pin, Row Spacing 7.62 mm, Pitch 2.54 mm)
pins: 1 NC, 2 HYST (oe), 3 THRE (in), 4 OUT (out), 5 GND (power), 6 NC, 7 NC, 8 VCC (power)

## MAX8212ESA
designator U?
Microprocessor Voltage Monitor with Programmable Voltage Detection
footprint NSO8_N (SOIC, 8-Leads, Body 4.9x3.9mm, Pitch 1.27mm, IPC Medium Density)
footprint NSO8_L (SOIC, 8-Leads, Body 4.9x3.9mm, Pitch 1.27mm, IPC High Density)
footprint NSO8_M (SOIC, 8-Leads, Body 4.9x3.9mm, Pitch 1.27mm, IPC Low Density)
3D model NSO8 (8-Pin Small Outline Integrated Circuit 1.27 mm Pitch)
pins: 1 NC, 2 HYST (oe), 3 THRE (in), 4 OUT (out), 5 GND (power), 6 NC, 7 NC, 8 VCC (power)

## MAX8212ETY
designator U?
Microprocessor Voltage Monitor with Programmable Voltage Detection
footprint TO-99 (Can; 8 Leads; Pin Circle Dia. 5.08 mm; Lead Dia. 0.48 mm (max))
pins: 1 THRE (in), 2 OUT (oc), 3 NC, 4 GND (power), 5 NC, 6 NC, 7 VCC (power), 8 HYST (oe)

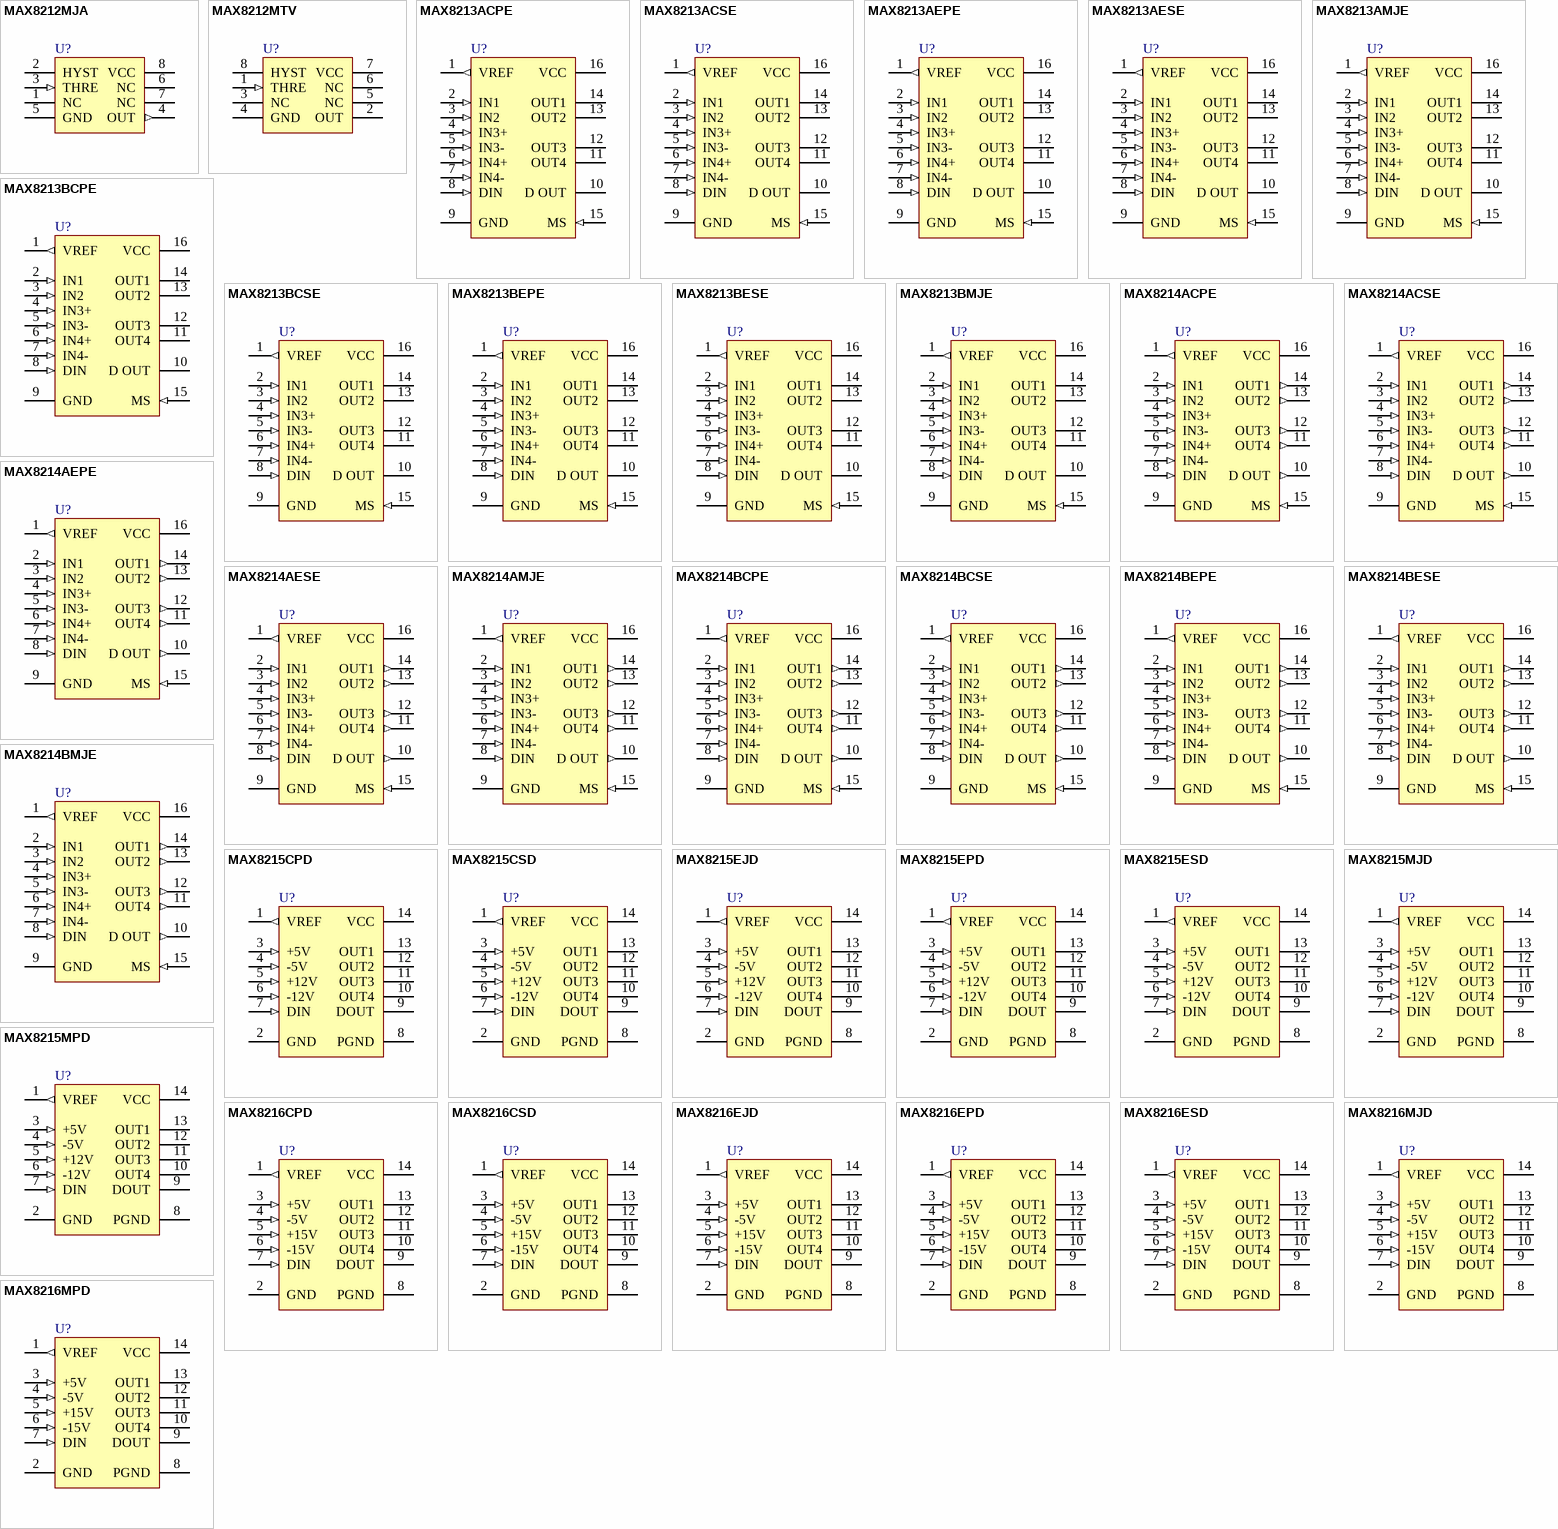
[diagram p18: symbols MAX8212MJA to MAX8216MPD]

## MAX8212MJA
designator U?
Microprocessor Voltage Monitor with Programmable Voltage Detection
footprint JA8 (DIP, 8-Leads, Row Spacing 7.62mm, Pitch 2.54mm, Body 9.91x6.73mm)
3D model PA8 (DIP, 8-Pin, Row Spacing 7.62 mm, Pitch 2.54 mm)
pins: 1 NC, 2 HYST (oe), 3 THRE (in), 4 OUT (out), 5 GND (power), 6 NC, 7 NC, 8 VCC (power)

## MAX8212MTV
designator U?
Microprocessor Voltage Monitor with Programmable Voltage Detection
footprint TO-99 (Can; 8 Leads; Pin Circle Dia. 5.08 mm; Lead Dia. 0.48 mm (max))
pins: 1 THRE (in), 2 OUT (oc), 3 NC, 4 GND (power), 5 NC, 6 NC, 7 VCC (power), 8 HYST (oe)

## MAX8213ACPE
designator U?
Five Universal Voltage Monitors-Complete Microprocessor Voltage Monitoring
footprint PE16A (DIP, 16-Leads, Row Spacing 7.62mm, Pitch 2.54mm, Body 19.18x6.99mm)
3D model PE16 (DIP, 16-Pin, Row Spacing 7.62 mm, Pitch 2.54 mm)
pins: 1 VREF (out), 2 IN1 (in), 3 IN2 (in), 4 IN3+ (in), 5 IN3- (in), 6 IN4+ (in), 7 IN4- (in), 8 DIN (in), 9 GND (power), 10 D OUT (oc), 11 OUT4 (oc), 12 OUT3 (oc), 13 OUT2 (oc), 14 OUT1 (oc), 15 MS (in), 16 VCC (power)

## MAX8213ACSE
designator U?
Five Universal Voltage Monitors-Complete Microprocessor Voltage Monitoring
footprint NSO16_N (SOIC, 16-Leads, Body 9.9x3.9mm, Pitch 1.27mm, IPC Medium Density)
footprint NSO16_L (SOIC, 16-Leads, Body 9.9x3.9mm, Pitch 1.27mm, IPC High Density)
footprint NSO16_M (SOIC, 16-Leads, Body 9.9x3.9mm, Pitch 1.27mm, IPC Low Density)
3D model NSO16 (16-Pin Small Outline Integrated Circuit 1.27 mm Pitch)
pins: 1 VREF (out), 2 IN1 (in), 3 IN2 (in), 4 IN3+ (in), 5 IN3- (in), 6 IN4+ (in), 7 IN4- (in), 8 DIN (in), 9 GND (power), 10 D OUT (oc), 11 OUT4 (oc), 12 OUT3 (oc), 13 OUT2 (oc), 14 OUT1 (oc), 15 MS (in), 16 VCC (power)

## MAX8213AEPE
designator U?
Five Universal Voltage Monitors-Complete Microprocessor Voltage Monitoring
footprint PE16A (DIP, 16-Leads, Row Spacing 7.62mm, Pitch 2.54mm, Body 19.18x6.99mm)
3D model PE16 (DIP, 16-Pin, Row Spacing 7.62 mm, Pitch 2.54 mm)
pins: 1 VREF (out), 2 IN1 (in), 3 IN2 (in), 4 IN3+ (in), 5 IN3- (in), 6 IN4+ (in), 7 IN4- (in), 8 DIN (in), 9 GND (power), 10 D OUT (oc), 11 OUT4 (oc), 12 OUT3 (oc), 13 OUT2 (oc), 14 OUT1 (oc), 15 MS (in), 16 VCC (power)

## MAX8213AESE
designator U?
Five Universal Voltage Monitors-Complete Microprocessor Voltage Monitoring
footprint NSO16_N (SOIC, 16-Leads, Body 9.9x3.9mm, Pitch 1.27mm, IPC Medium Density)
footprint NSO16_L (SOIC, 16-Leads, Body 9.9x3.9mm, Pitch 1.27mm, IPC High Density)
footprint NSO16_M (SOIC, 16-Leads, Body 9.9x3.9mm, Pitch 1.27mm, IPC Low Density)
3D model NSO16 (16-Pin Small Outline Integrated Circuit 1.27 mm Pitch)
pins: 1 VREF (out), 2 IN1 (in), 3 IN2 (in), 4 IN3+ (in), 5 IN3- (in), 6 IN4+ (in), 7 IN4- (in), 8 DIN (in), 9 GND (power), 10 D OUT (oc), 11 OUT4 (oc), 12 OUT3 (oc), 13 OUT2 (oc), 14 OUT1 (oc), 15 MS (in), 16 VCC (power)

## MAX8213AMJE
designator U?
Five Universal Voltage Monitors-Complete Microprocessor Voltage Monitoring
footprint JE16 (DIP, 16-Leads, Row Spacing 7.62mm, Pitch 2.54mm, Body 20.37x6.73mm)
3D model JE16 (DIP, 16-Pin, Row Spacing 7.62 mm, Pitch 2.54 mm)
pins: 1 VREF (out), 2 IN1 (in), 3 IN2 (in), 4 IN3+ (in), 5 IN3- (in), 6 IN4+ (in), 7 IN4- (in), 8 DIN (in), 9 GND (power), 10 D OUT (oc), 11 OUT4 (oc), 12 OUT3 (oc), 13 OUT2 (oc), 14 OUT1 (oc), 15 MS (in), 16 VCC (power)

## MAX8213BCPE
designator U?
Five Universal Voltage Monitors-Complete Microprocessor Voltage Monitoring
footprint PE16A (DIP, 16-Leads, Row Spacing 7.62mm, Pitch 2.54mm, Body 19.18x6.99mm)
3D model PE16 (DIP, 16-Pin, Row Spacing 7.62 mm, Pitch 2.54 mm)
pins: 1 VREF (out), 2 IN1 (in), 3 IN2 (in), 4 IN3+ (in), 5 IN3- (in), 6 IN4+ (in), 7 IN4- (in), 8 DIN (in), 9 GND (power), 10 D OUT (oc), 11 OUT4 (oc), 12 OUT3 (oc), 13 OUT2 (oc), 14 OUT1 (oc), 15 MS (in), 16 VCC (power)

## MAX8213BCSE
designator U?
Five Universal Voltage Monitors-Complete Microprocessor Voltage Monitoring
footprint NSO16_N (SOIC, 16-Leads, Body 9.9x3.9mm, Pitch 1.27mm, IPC Medium Density)
footprint NSO16_L (SOIC, 16-Leads, Body 9.9x3.9mm, Pitch 1.27mm, IPC High Density)
footprint NSO16_M (SOIC, 16-Leads, Body 9.9x3.9mm, Pitch 1.27mm, IPC Low Density)
3D model NSO16 (16-Pin Small Outline Integrated Circuit 1.27 mm Pitch)
pins: 1 VREF (out), 2 IN1 (in), 3 IN2 (in), 4 IN3+ (in), 5 IN3- (in), 6 IN4+ (in), 7 IN4- (in), 8 DIN (in), 9 GND (power), 10 D OUT (oc), 11 OUT4 (oc), 12 OUT3 (oc), 13 OUT2 (oc), 14 OUT1 (oc), 15 MS (in), 16 VCC (power)

## MAX8213BEPE
designator U?
Five Universal Voltage Monitors-Complete Microprocessor Voltage Monitoring
footprint PE16A (DIP, 16-Leads, Row Spacing 7.62mm, Pitch 2.54mm, Body 19.18x6.99mm)
3D model PE16 (DIP, 16-Pin, Row Spacing 7.62 mm, Pitch 2.54 mm)
pins: 1 VREF (out), 2 IN1 (in), 3 IN2 (in), 4 IN3+ (in), 5 IN3- (in), 6 IN4+ (in), 7 IN4- (in), 8 DIN (in), 9 GND (power), 10 D OUT (oc), 11 OUT4 (oc), 12 OUT3 (oc), 13 OUT2 (oc), 14 OUT1 (oc), 15 MS (in), 16 VCC (power)

## MAX8213BESE
designator U?
Five Universal Voltage Monitors-Complete Microprocessor Voltage Monitoring
footprint NSO16_N (SOIC, 16-Leads, Body 9.9x3.9mm, Pitch 1.27mm, IPC Medium Density)
footprint NSO16_L (SOIC, 16-Leads, Body 9.9x3.9mm, Pitch 1.27mm, IPC High Density)
footprint NSO16_M (SOIC, 16-Leads, Body 9.9x3.9mm, Pitch 1.27mm, IPC Low Density)
3D model NSO16 (16-Pin Small Outline Integrated Circuit 1.27 mm Pitch)
pins: 1 VREF (out), 2 IN1 (in), 3 IN2 (in), 4 IN3+ (in), 5 IN3- (in), 6 IN4+ (in), 7 IN4- (in), 8 DIN (in), 9 GND (power), 10 D OUT (oc), 11 OUT4 (oc), 12 OUT3 (oc), 13 OUT2 (oc), 14 OUT1 (oc), 15 MS (in), 16 VCC (power)

## MAX8213BMJE
designator U?
Five Universal Voltage Monitors-Complete Microprocessor Voltage Monitoring
footprint JE16 (DIP, 16-Leads, Row Spacing 7.62mm, Pitch 2.54mm, Body 20.37x6.73mm)
3D model JE16 (DIP, 16-Pin, Row Spacing 7.62 mm, Pitch 2.54 mm)
pins: 1 VREF (out), 2 IN1 (in), 3 IN2 (in), 4 IN3+ (in), 5 IN3- (in), 6 IN4+ (in), 7 IN4- (in), 8 DIN (in), 9 GND (power), 10 D OUT (oc), 11 OUT4 (oc), 12 OUT3 (oc), 13 OUT2 (oc), 14 OUT1 (oc), 15 MS (in), 16 VCC (power)

## MAX8214ACPE
designator U?
Five Universal Voltage Monitors-Complete Microprocessor Voltage Monitoring
footprint PE16A (DIP, 16-Leads, Row Spacing 7.62mm, Pitch 2.54mm, Body 19.18x6.99mm)
3D model PE16 (DIP, 16-Pin, Row Spacing 7.62 mm, Pitch 2.54 mm)
pins: 1 VREF (out), 2 IN1 (in), 3 IN2 (in), 4 IN3+ (in), 5 IN3- (in), 6 IN4+ (in), 7 IN4- (in), 8 DIN (in), 9 GND (power), 10 D OUT (out), 11 OUT4 (out), 12 OUT3 (out), 13 OUT2 (out), 14 OUT1 (out), 15 MS (in), 16 VCC (power)

## MAX8214ACSE
designator U?
Five Universal Voltage Monitors-Complete Microprocessor Voltage Monitoring
footprint NSO16_N (SOIC, 16-Leads, Body 9.9x3.9mm, Pitch 1.27mm, IPC Medium Density)
footprint NSO16_L (SOIC, 16-Leads, Body 9.9x3.9mm, Pitch 1.27mm, IPC High Density)
footprint NSO16_M (SOIC, 16-Leads, Body 9.9x3.9mm, Pitch 1.27mm, IPC Low Density)
3D model NSO16 (16-Pin Small Outline Integrated Circuit 1.27 mm Pitch)
pins: 1 VREF (out), 2 IN1 (in), 3 IN2 (in), 4 IN3+ (in), 5 IN3- (in), 6 IN4+ (in), 7 IN4- (in), 8 DIN (in), 9 GND (power), 10 D OUT (out), 11 OUT4 (out), 12 OUT3 (out), 13 OUT2 (out), 14 OUT1 (out), 15 MS (in), 16 VCC (power)

## MAX8214AEPE
designator U?
Five Universal Voltage Monitors-Complete Microprocessor Voltage Monitoring
footprint PE16A (DIP, 16-Leads, Row Spacing 7.62mm, Pitch 2.54mm, Body 19.18x6.99mm)
3D model PE16 (DIP, 16-Pin, Row Spacing 7.62 mm, Pitch 2.54 mm)
pins: 1 VREF (out), 2 IN1 (in), 3 IN2 (in), 4 IN3+ (in), 5 IN3- (in), 6 IN4+ (in), 7 IN4- (in), 8 DIN (in), 9 GND (power), 10 D OUT (out), 11 OUT4 (out), 12 OUT3 (out), 13 OUT2 (out), 14 OUT1 (out), 15 MS (in), 16 VCC (power)

## MAX8214AESE
designator U?
Five Universal Voltage Monitors-Complete Microprocessor Voltage Monitoring
footprint NSO16_N (SOIC, 16-Leads, Body 9.9x3.9mm, Pitch 1.27mm, IPC Medium Density)
footprint NSO16_L (SOIC, 16-Leads, Body 9.9x3.9mm, Pitch 1.27mm, IPC High Density)
footprint NSO16_M (SOIC, 16-Leads, Body 9.9x3.9mm, Pitch 1.27mm, IPC Low Density)
3D model NSO16 (16-Pin Small Outline Integrated Circuit 1.27 mm Pitch)
pins: 1 VREF (out), 2 IN1 (in), 3 IN2 (in), 4 IN3+ (in), 5 IN3- (in), 6 IN4+ (in), 7 IN4- (in), 8 DIN (in), 9 GND (power), 10 D OUT (out), 11 OUT4 (out), 12 OUT3 (out), 13 OUT2 (out), 14 OUT1 (out), 15 MS (in), 16 VCC (power)

## MAX8214AMJE
designator U?
Five Universal Voltage Monitors-Complete Microprocessor Voltage Monitoring
footprint JE16 (DIP, 16-Leads, Row Spacing 7.62mm, Pitch 2.54mm, Body 20.37x6.73mm)
3D model JE16 (DIP, 16-Pin, Row Spacing 7.62 mm, Pitch 2.54 mm)
pins: 1 VREF (out), 2 IN1 (in), 3 IN2 (in), 4 IN3+ (in), 5 IN3- (in), 6 IN4+ (in), 7 IN4- (in), 8 DIN (in), 9 GND (power), 10 D OUT (out), 11 OUT4 (out), 12 OUT3 (out), 13 OUT2 (out), 14 OUT1 (out), 15 MS (in), 16 VCC (power)

## MAX8214BCPE
designator U?
Five Universal Voltage Monitors-Complete Microprocessor Voltage Monitoring
footprint PE16A (DIP, 16-Leads, Row Spacing 7.62mm, Pitch 2.54mm, Body 19.18x6.99mm)
3D model PE16 (DIP, 16-Pin, Row Spacing 7.62 mm, Pitch 2.54 mm)
pins: 1 VREF (out), 2 IN1 (in), 3 IN2 (in), 4 IN3+ (in), 5 IN3- (in), 6 IN4+ (in), 7 IN4- (in), 8 DIN (in), 9 GND (power), 10 D OUT (out), 11 OUT4 (out), 12 OUT3 (out), 13 OUT2 (out), 14 OUT1 (out), 15 MS (in), 16 VCC (power)

## MAX8214BCSE
designator U?
Five Universal Voltage Monitors-Complete Microprocessor Voltage Monitoring
footprint NSO16_N (SOIC, 16-Leads, Body 9.9x3.9mm, Pitch 1.27mm, IPC Medium Density)
footprint NSO16_L (SOIC, 16-Leads, Body 9.9x3.9mm, Pitch 1.27mm, IPC High Density)
footprint NSO16_M (SOIC, 16-Leads, Body 9.9x3.9mm, Pitch 1.27mm, IPC Low Density)
3D model NSO16 (16-Pin Small Outline Integrated Circuit 1.27 mm Pitch)
pins: 1 VREF (out), 2 IN1 (in), 3 IN2 (in), 4 IN3+ (in), 5 IN3- (in), 6 IN4+ (in), 7 IN4- (in), 8 DIN (in), 9 GND (power), 10 D OUT (out), 11 OUT4 (out), 12 OUT3 (out), 13 OUT2 (out), 14 OUT1 (out), 15 MS (in), 16 VCC (power)

## MAX8214BEPE
designator U?
Five Universal Voltage Monitors-Complete Microprocessor Voltage Monitoring
footprint PE16A (DIP, 16-Leads, Row Spacing 7.62mm, Pitch 2.54mm, Body 19.18x6.99mm)
3D model PE16 (DIP, 16-Pin, Row Spacing 7.62 mm, Pitch 2.54 mm)
pins: 1 VREF (out), 2 IN1 (in), 3 IN2 (in), 4 IN3+ (in), 5 IN3- (in), 6 IN4+ (in), 7 IN4- (in), 8 DIN (in), 9 GND (power), 10 D OUT (out), 11 OUT4 (out), 12 OUT3 (out), 13 OUT2 (out), 14 OUT1 (out), 15 MS (in), 16 VCC (power)

## MAX8214BESE
designator U?
Five Universal Voltage Monitors-Complete Microprocessor Voltage Monitoring
footprint NSO16_N (SOIC, 16-Leads, Body 9.9x3.9mm, Pitch 1.27mm, IPC Medium Density)
footprint NSO16_L (SOIC, 16-Leads, Body 9.9x3.9mm, Pitch 1.27mm, IPC High Density)
footprint NSO16_M (SOIC, 16-Leads, Body 9.9x3.9mm, Pitch 1.27mm, IPC Low Density)
3D model NSO16 (16-Pin Small Outline Integrated Circuit 1.27 mm Pitch)
pins: 1 VREF (out), 2 IN1 (in), 3 IN2 (in), 4 IN3+ (in), 5 IN3- (in), 6 IN4+ (in), 7 IN4- (in), 8 DIN (in), 9 GND (power), 10 D OUT (out), 11 OUT4 (out), 12 OUT3 (out), 13 OUT2 (out), 14 OUT1 (out), 15 MS (in), 16 VCC (power)

## MAX8214BMJE
designator U?
Five Universal Voltage Monitors-Complete Microprocessor Voltage Monitoring
footprint JE16 (DIP, 16-Leads, Row Spacing 7.62mm, Pitch 2.54mm, Body 20.37x6.73mm)
3D model JE16 (DIP, 16-Pin, Row Spacing 7.62 mm, Pitch 2.54 mm)
pins: 1 VREF (out), 2 IN1 (in), 3 IN2 (in), 4 IN3+ (in), 5 IN3- (in), 6 IN4+ (in), 7 IN4- (in), 8 DIN (in), 9 GND (power), 10 D OUT (out), 11 OUT4 (out), 12 OUT3 (out), 13 OUT2 (out), 14 OUT1 (out), 15 MS (in), 16 VCC (power)

## MAX8215CPD
designator U?
±12V Dedicated Microprocessor Voltage Monitor
footprint PD14 (DIP, 14-Leads, Row Spacing 7.62mm, Pitch 2.54mm, Body 19.05x7.24mm)
3D model PD14 (DIP, 14-Pin, Row Spacing 7.62 mm, Pitch 2.54 mm)
pins: 1 VREF (out), 2 GND (power), 3 +5V (in), 4 -5V (in), 5 +12V (in), 6 -12V (in), 7 DIN (in), 8 PGND (power), 9 DOUT (oc), 10 OUT4 (oc), 11 OUT3 (oc), 12 OUT2 (oc), 13 OUT1 (oc), 14 VCC (power)

## MAX8215CSD
designator U?
±12V Dedicated Microprocessor Voltage Monitor
footprint NSO14_N (SOIC, 14-Leads, Body 8.7x3.9mm, Pitch 1.27mm, IPC Medium Density)
footprint NSO14_L (SOIC, 14-Leads, Body 8.7x3.9mm, Pitch 1.27mm, IPC High Density)
footprint NSO14_M (SOIC, 14-Leads, Body 8.7x3.9mm, Pitch 1.27mm, IPC Low Density)
3D model NSO14 (14-Pin Small Outline Integrated Circuit 1.27 mm Pitch)
pins: 1 VREF (out), 2 GND (power), 3 +5V (in), 4 -5V (in), 5 +12V (in), 6 -12V (in), 7 DIN (in), 8 PGND (power), 9 DOUT (oc), 10 OUT4 (oc), 11 OUT3 (oc), 12 OUT2 (oc), 13 OUT1 (oc), 14 VCC (power)

## MAX8215EJD
designator U?
±12V Dedicated Microprocessor Voltage Monitor
footprint JD14 (DIP, 14-Leads, Row Spacing 7.62mm, Pitch 2.54mm, Body 19.56x6.73mm)
3D model JD14 (DIP, 14-Pin, Row Spacing 7.62 mm, Pitch 2.54 mm)
pins: 1 VREF (out), 2 GND (power), 3 +5V (in), 4 -5V (in), 5 +12V (in), 6 -12V (in), 7 DIN (in), 8 PGND (power), 9 DOUT (oc), 10 OUT4 (oc), 11 OUT3 (oc), 12 OUT2 (oc), 13 OUT1 (oc), 14 VCC (power)

## MAX8215EPD
designator U?
±12V Dedicated Microprocessor Voltage Monitor
footprint PD14 (DIP, 14-Leads, Row Spacing 7.62mm, Pitch 2.54mm, Body 19.05x7.24mm)
3D model PD14 (DIP, 14-Pin, Row Spacing 7.62 mm, Pitch 2.54 mm)
pins: 1 VREF (out), 2 GND (power), 3 +5V (in), 4 -5V (in), 5 +12V (in), 6 -12V (in), 7 DIN (in), 8 PGND (power), 9 DOUT (oc), 10 OUT4 (oc), 11 OUT3 (oc), 12 OUT2 (oc), 13 OUT1 (oc), 14 VCC (power)

## MAX8215ESD
designator U?
±12V Dedicated Microprocessor Voltage Monitor
footprint NSO14_N (SOIC, 14-Leads, Body 8.7x3.9mm, Pitch 1.27mm, IPC Medium Density)
footprint NSO14_L (SOIC, 14-Leads, Body 8.7x3.9mm, Pitch 1.27mm, IPC High Density)
footprint NSO14_M (SOIC, 14-Leads, Body 8.7x3.9mm, Pitch 1.27mm, IPC Low Density)
3D model NSO14 (14-Pin Small Outline Integrated Circuit 1.27 mm Pitch)
pins: 1 VREF (out), 2 GND (power), 3 +5V (in), 4 -5V (in), 5 +12V (in), 6 -12V (in), 7 DIN (in), 8 PGND (power), 9 DOUT (oc), 10 OUT4 (oc), 11 OUT3 (oc), 12 OUT2 (oc), 13 OUT1 (oc), 14 VCC (power)

## MAX8215MJD
designator U?
±12V Dedicated Microprocessor Voltage Monitor
footprint JD14 (DIP, 14-Leads, Row Spacing 7.62mm, Pitch 2.54mm, Body 19.56x6.73mm)
3D model JD14 (DIP, 14-Pin, Row Spacing 7.62 mm, Pitch 2.54 mm)
pins: 1 VREF (out), 2 GND (power), 3 +5V (in), 4 -5V (in), 5 +12V (in), 6 -12V (in), 7 DIN (in), 8 PGND (power), 9 DOUT (oc), 10 OUT4 (oc), 11 OUT3 (oc), 12 OUT2 (oc), 13 OUT1 (oc), 14 VCC (power)

## MAX8215MPD
designator U?
±12V Dedicated Microprocessor Voltage Monitor
footprint PD14 (DIP, 14-Leads, Row Spacing 7.62mm, Pitch 2.54mm, Body 19.05x7.24mm)
3D model PD14 (DIP, 14-Pin, Row Spacing 7.62 mm, Pitch 2.54 mm)
pins: 1 VREF (out), 2 GND (power), 3 +5V (in), 4 -5V (in), 5 +12V (in), 6 -12V (in), 7 DIN (in), 8 PGND (power), 9 DOUT (oc), 10 OUT4 (oc), 11 OUT3 (oc), 12 OUT2 (oc), 13 OUT1 (oc), 14 VCC (power)

## MAX8216CPD
designator U?
±15V Dedicated Microprocessor Voltage Monitor
footprint PD14 (DIP, 14-Leads, Row Spacing 7.62mm, Pitch 2.54mm, Body 19.05x7.24mm)
3D model PD14 (DIP, 14-Pin, Row Spacing 7.62 mm, Pitch 2.54 mm)
pins: 1 VREF (out), 2 GND (power), 3 +5V (in), 4 -5V (in), 5 +15V (in), 6 -15V (in), 7 DIN (in), 8 PGND (power), 9 DOUT (oc), 10 OUT4 (oc), 11 OUT3 (oc), 12 OUT2 (oc), 13 OUT1 (oc), 14 VCC (power)

## MAX8216CSD
designator U?
±15V Dedicated Microprocessor Voltage Monitor
footprint NSO14_N (SOIC, 14-Leads, Body 8.7x3.9mm, Pitch 1.27mm, IPC Medium Density)
footprint NSO14_L (SOIC, 14-Leads, Body 8.7x3.9mm, Pitch 1.27mm, IPC High Density)
footprint NSO14_M (SOIC, 14-Leads, Body 8.7x3.9mm, Pitch 1.27mm, IPC Low Density)
3D model NSO14 (14-Pin Small Outline Integrated Circuit 1.27 mm Pitch)
pins: 1 VREF (out), 2 GND (power), 3 +5V (in), 4 -5V (in), 5 +15V (in), 6 -15V (in), 7 DIN (in), 8 PGND (power), 9 DOUT (oc), 10 OUT4 (oc), 11 OUT3 (oc), 12 OUT2 (oc), 13 OUT1 (oc), 14 VCC (power)

## MAX8216EJD
designator U?
±15V Dedicated Microprocessor Voltage Monitor
footprint JD14 (DIP, 14-Leads, Row Spacing 7.62mm, Pitch 2.54mm, Body 19.56x6.73mm)
3D model JD14 (DIP, 14-Pin, Row Spacing 7.62 mm, Pitch 2.54 mm)
pins: 1 VREF (out), 2 GND (power), 3 +5V (in), 4 -5V (in), 5 +15V (in), 6 -15V (in), 7 DIN (in), 8 PGND (power), 9 DOUT (oc), 10 OUT4 (oc), 11 OUT3 (oc), 12 OUT2 (oc), 13 OUT1 (oc), 14 VCC (power)

## MAX8216EPD
designator U?
±15V Dedicated Microprocessor Voltage Monitor
footprint PD14 (DIP, 14-Leads, Row Spacing 7.62mm, Pitch 2.54mm, Body 19.05x7.24mm)
3D model PD14 (DIP, 14-Pin, Row Spacing 7.62 mm, Pitch 2.54 mm)
pins: 1 VREF (out), 2 GND (power), 3 +5V (in), 4 -5V (in), 5 +15V (in), 6 -15V (in), 7 DIN (in), 8 PGND (power), 9 DOUT (oc), 10 OUT4 (oc), 11 OUT3 (oc), 12 OUT2 (oc), 13 OUT1 (oc), 14 VCC (power)

## MAX8216ESD
designator U?
±15V Dedicated Microprocessor Voltage Monitor
footprint NSO14_N (SOIC, 14-Leads, Body 8.7x3.9mm, Pitch 1.27mm, IPC Medium Density)
footprint NSO14_L (SOIC, 14-Leads, Body 8.7x3.9mm, Pitch 1.27mm, IPC High Density)
footprint NSO14_M (SOIC, 14-Leads, Body 8.7x3.9mm, Pitch 1.27mm, IPC Low Density)
3D model NSO14 (14-Pin Small Outline Integrated Circuit 1.27 mm Pitch)
pins: 1 VREF (out), 2 GND (power), 3 +5V (in), 4 -5V (in), 5 +15V (in), 6 -15V (in), 7 DIN (in), 8 PGND (power), 9 DOUT (oc), 10 OUT4 (oc), 11 OUT3 (oc), 12 OUT2 (oc), 13 OUT1 (oc), 14 VCC (power)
